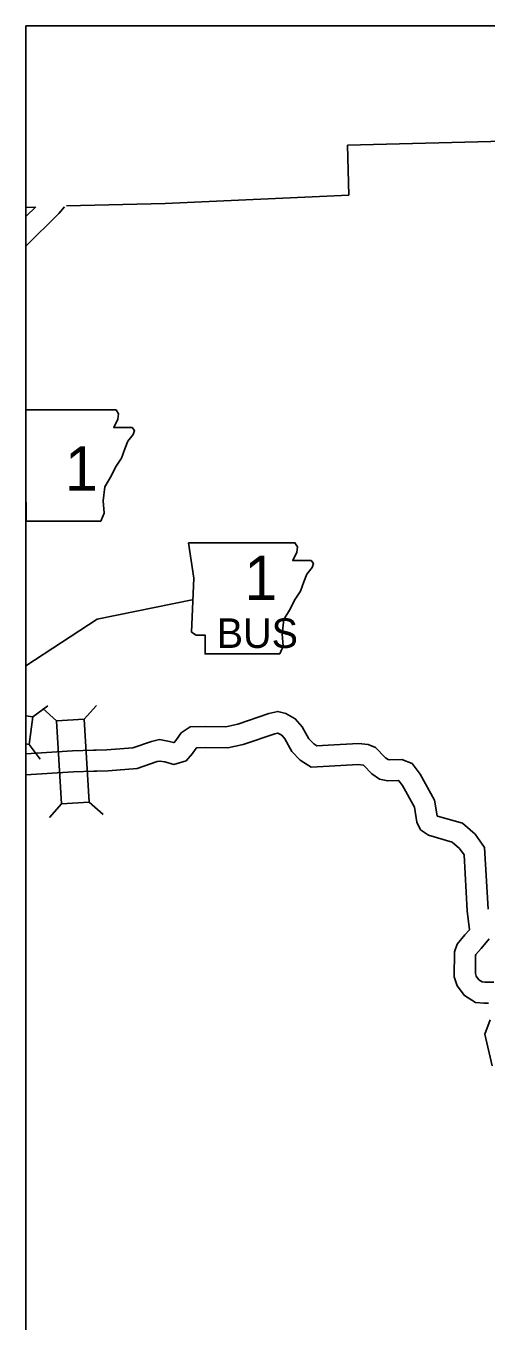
# Model space of a CAD drawing. Extents: x 1720274 to 1751788, y 372074 to 391887.
# Drawn here: x 1720610 to 1721650, y 388322 to 391250 of the extents above; entities that cross this region are included whole.
import ezdxf

# ---------------------------------------------------------------- set-up
doc = ezdxf.new("R2010")
doc.units = 0
for name, color, linetype in [('Level 10', 7, 'Continuous'), ('Level 2', 7, 'Continuous'), ('Level 20', 7, 'Continuous'), ('Level 21', 7, 'Continuous'), ('R_Draft', 7, 'Continuous')]:
    doc.layers.add(name, color=color, linetype=linetype)

msp = doc.modelspace()

# ---------------------------------------------------------------- linework, layer by layer
at = {"layer": 'Level 10'}
for points in [[(1720610.3, 390751.7), (1720684.5, 390825.8), (1720697.2, 390841)], [(1720610.3, 390818.8), (1720632.4, 390840.8)], [(1720610.3, 389604.4), (1720715.6, 389610.8), (1720762.7, 389612.3), (1720769.4, 389612.3), (1720793.2, 389613.3), (1720852.1, 389617.7), (1720893.9, 389632.5), (1720912, 389636.4), (1720934.4, 389632.4), (1720944.1, 389629.7), (1720945.5, 389630.2), (1720949.1, 389634.3), (1720961, 389651.6), (1720981.2, 389665.3), (1721015.5, 389666.4), (1721062.2, 389665.6), (1721088.8, 389671.1), (1721159.4, 389695.3), (1721179.4, 389700.1), (1721197.2, 389695.3), (1721218.9, 389683.8), (1721234.4, 389665.2), (1721249.5, 389638.5), (1721260.6, 389626.9), (1721267.5, 389622.5), (1721293.1, 389623.7), (1721361.7, 389627.5), (1721383.6, 389625.3), (1721399.9, 389618.6), (1721422.6, 389595.7), (1721428.6, 389591.5), (1721432.4, 389590.6), (1721459.6, 389591.5), (1721482.7, 389582.7), (1721500.7, 389558.7), (1721533.2, 389499.8), (1721539.2, 389464.2), (1721540, 389463.7), (1721596.8, 389447.3), (1721625, 389422.7), (1721646.6, 389392.3), (1721654.7, 389253.2)], [(1720610.3, 389556.9), (1720717.8, 389563.4), (1720763.7, 389564.9), (1720770.5, 389564.9), (1720795.9, 389565.9), (1720861.9, 389570.9), (1720906.9, 389586.8), (1720912.9, 389588.1), (1720923.8, 389586.2), (1720944.7, 389580.4), (1720972.3, 389588.8), (1720986.7, 389605.2), (1720995, 389617.4), (1720996.4, 389618.3), (1721015.9, 389619), (1721066.8, 389618.1), (1721101.3, 389625.3), (1721172.7, 389649.8), (1721178.7, 389651.2), (1721179.7, 389650.9), (1721188.4, 389646.3), (1721195.3, 389638.1), (1721211.2, 389610), (1721230.2, 389590.2), (1721254.5, 389574.4), (1721295.5, 389576.3), (1721360.6, 389580), (1721372, 389578.8), (1721373, 389578.4), (1721392, 389559.3), (1721408.9, 389547.4), (1721427.7, 389543), (1721451.6, 389543.8), (1721453, 389543.2), (1721460.8, 389532.9), (1721487.8, 389484), (1721493.5, 389450.3), (1721501.4, 389432.7), (1721519.6, 389420.2), (1721573.6, 389404.7), (1721589.6, 389390.7), (1721600.1, 389376), (1721607.4, 389249.3), (1721612.1, 389206.5), (1721602.2, 389195.1), (1721584.8, 389174.2), (1721578.9, 389156.6), (1721578.1, 389100.7), (1721584.7, 389079.8), (1721601, 389058), (1721625.6, 389042.5), (1721644.8, 389040.7), (1721655.7, 389040.7)], [(1721656.8, 389185.9), (1721638.4, 389164.4), (1721626.9, 389150.7), (1721626.2, 389148.6), (1721625.6, 389107.7), (1721627.5, 389101.6), (1721633.7, 389093.4), (1721641.2, 389088.7), (1721647, 389088.1), (1721667.1, 389088.1)], [(1721659.2, 389003.3), (1721647, 388970.7), (1721663.4, 388899.2)]]:
    msp.add_lwpolyline(points, dxfattribs=at)
at = {"layer": 'Level 2'}
for points in [[(1720701.8, 390842.8), (1720925, 390848.4), (1721339.8, 390867.2), (1721336.9, 390979.9), (1721719.6, 390989.9), (1722141.5, 391004.1), (1722148.7, 391004.5), (1722230.7, 391008.8)], [(1720610.3, 390839.5), (1720630.3, 390840.3)]]:
    msp.add_lwpolyline(points, dxfattribs=at)
at = {"layer": 'Level 20'}
for p, q in [((1720626.3, 389687.7), (1720659.7, 389712.8)), ((1720679.8, 389678.9), (1720648.6, 389706.5)), ((1720742.2, 389682.7), (1720769.9, 389713.9)), ((1720617.6, 389625.7), (1720642.7, 389592.4)), ((1720691.1, 389491.5), (1720663.5, 389460.3)), ((1720753.6, 389495.3), (1720784.8, 389467.6))]:
    msp.add_line(p, q, dxfattribs=at)
msp.add_lwpolyline([(1720610.3, 389626.8), (1720617.6, 389625.7), (1720626.3, 389687.7), (1720610.3, 389690)], dxfattribs=at)
msp.add_lwpolyline([(1720679.8, 389678.9), (1720691.1, 389491.5), (1720753.6, 389495.3), (1720742.2, 389682.7)], close=True, dxfattribs=at)
at = {"layer": 'Level 21'}
msp.add_line((1721218.3, 390081.4), (1721218.3, 390081.4), dxfattribs=at)
msp.add_line((1721218.3, 390081.4), (1721218.3, 390081.4), dxfattribs=at)
for points in [[(1720610.3, 390173.4), (1720610.9, 390173.4), (1720610.9, 390130.6), (1720779.3, 390130.6), (1720787.4, 390148), (1720784.7, 390176.1), (1720788.7, 390208.2), (1720803.4, 390233.5), (1720812.8, 390252.3), (1720826.1, 390272.3), (1720834.1, 390293.7), (1720840.8, 390311.1), (1720852.9, 390325.8), (1720855.5, 390335.1), (1720850.2, 390341.8), (1720808.7, 390341.8), (1720818.1, 390360.5), (1720819.4, 390372.5), (1720813.9, 390381.8), (1720610.3, 390381.9)], [(1720610.3, 389803.2), (1720771.2, 389908.8), (1720986, 389952.4)]]:
    msp.add_lwpolyline(points, dxfattribs=at)
msp.add_lwpolyline([(1720977.8, 390081.4), (1720989.8, 390001.2), (1720984.5, 389879.6), (1720995.2, 389872.9), (1721015.2, 389872.9), (1721015.2, 389830.2), (1721183.6, 389830.2), (1721191.6, 389847.5), (1721188.9, 389875.6), (1721193, 389907.7), (1721207.7, 389933.1), (1721217, 389951.8), (1721230.4, 389971.8), (1721238.4, 389993.2), (1721245.1, 390010.6), (1721257.1, 390025.3), (1721259.8, 390034.6), (1721254.4, 390041.3), (1721213, 390041.3), (1721222.4, 390060), (1721223.7, 390072.1), (1721218.2, 390081.3)], close=True, dxfattribs=at)
at = {"layer": 'R_Draft'}
msp.add_lwpolyline([(1720610.3, 391249.6), (1726741.8, 391249.6), (1726741.8, 384893.1), (1720610.3, 384893.1)], close=True, dxfattribs=at)

# ---------------------------------------------------------------- texts
at = {"layer": 'Level 21'}
for s, height, p in [('1', 100.1, (1720698.4, 390199)), ('1', 100.1, (1721103.8, 389951.8)), ('BUS', 66.74, (1721041.4, 389843.7))]:
    msp.add_text(s, height=height, dxfattribs=at).set_placement(p)

doc.saveas('drawing.dxf')
